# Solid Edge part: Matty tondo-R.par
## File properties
Title: Matty tondo/R
Author: DESYS
Template: Normal.par
Last saved by: i.fialdini
Revision: 7
Application: Solid Edge
Tipo di contenuto documento: 0
Precisione: 0,990
Document Number: 8055/R
Revision: 0
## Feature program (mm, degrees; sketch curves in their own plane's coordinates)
sketch for "unnamed RevolvedProtrusion 1" plane through (0, 0, 0) normal (0, -1, 0) x-axis (1, 0, 0)
  line (-103.4736, -287.9981) -> (-155.4991, -287.9981)
  arc centre (-155.4991, -282.9981) radius 5 from (-160, -285.1756) to (-155.4991, -287.9981) ccw
  arc centre (470.1318, 19.6751) radius 700 from (-229.7225, 5.3909) to (-160, -285.1756) ccw
  arc centre (-224.7235, 5.4929) radius 5 from (-223.4856, 10.3372) to (-229.7225, 5.3909) ccw
  line (-223.4856, 10.3372) -> (-198.051, 3.8378)
  arc centre (-199.2889, -1.0065) radius 5 from (-194.3913, 0.0001) to (-198.051, 3.8378) ccw
  arc centre (50.4896, 50.3322) radius 250 from (-194.3913, 0.0001) to (-25, -187.9981) ccw
  line (0, -187.9981) -> (-25, -187.9981)
  line (-30, -227.9981) -> (0, -227.9981)
  arc centre (-30, -222.9981) radius 5 from (-35, -222.9981) to (-30, -227.9981) ccw
  line (-35, -211.5908) -> (-35, -222.9981)
  arc centre (-40, -211.5908) radius 5 from (-35, -211.5908) to (-38.2474, -206.908) ccw
  arc centre (-20.7216, -160.0802) radius 50 from (-57.3248, -194.142) to (-38.2474, -206.908) ccw
  arc centre (-60.9851, -197.5482) radius 5 from (-57.3248, -194.142) to (-65.6708, -195.8034) ccw
  line (-98.7879, -284.7428) -> (-65.6708, -195.8034)
  arc centre (-103.4736, -282.9981) radius 5 from (-103.4736, -287.9981) to (-98.7879, -284.7428) ccw
revolve "unnamed RevolvedProtrusion 1" add full turn 360 deg about sketch line (0, -187.9981) -> (0, -227.9981)
sketch for "unnamed Protrusion 1" plane through (0, 0, 0) normal (0, 0, 1) x-axis (1, 0, 0)
  line (-160.4648, -109.7225) -> (160.4648, -109.7225)
extrude "unnamed Protrusion 1" add through along -normal
sketch for "unnamed RevolvedCutout 1" plane through (0, 0, 0) normal (1, 0, 0) x-axis (0, 1, 0)
  line (-227.1078, -42.4292) -> (-218.1082, -42.4292)
  arc centre (-218.1082, -32.4292) radius 10 from (-208.9001, -36.3292) to (-218.1082, -42.4292) cw
  line (-208.9001, -36.3292) -> (-202.1374, -20.3623)
  arc centre (-192.9293, -24.2623) radius 10 from (-202.1374, -20.3623) to (-192.9293, -14.2623) cw
  line (-192.9293, -14.2623) -> (-146.1087, -14.2623)
  arc centre (-146.1087, -24.2623) radius 10 from (-146.1087, -14.2623) to (-136.1087, -24.2623) cw
  line (-136.1087, -24.2623) -> (-136.1087, -135.0988)
  arc centre (-116.1087, -135.0988) radius 20 from (-136.1087, -135.0988) to (-130.3249, -149.1665) ccw
  line (-130.3249, -149.1665) -> (-70.73, -209.3904)
revolve "unnamed RevolvedCutout 1" cut finite
fillet "Rotondo_1" radius 5
fillet "Rotondo_2" radius 10
sketch for "Foro_1" plane through (0, 0, -187.9981) normal (0, 0, 1) x-axis (0, -1, 0)
  hole centre (0, 0) bore radius 25
hole "Foro_1" diameter 50 through
sketch for "Foro_2" plane through (0, -157.0547, 0) normal (0, 0, 1) x-axis (-1, 0, 0)
  hole centre (0, 12.6678) bore radius 17.5
hole "Foro_2" diameter 35 through
fillet "Rotondo_3" radius 3
fillet "Rotondo_4" radius 10
sketch for "Foro_3" plane through (0, 9.4953, -287.9981) normal (0, 0, -1) x-axis (0.461749, -0.887011, 0)
  hole centre (-49.0263, 114.7425) bore radius 7.5
hole "Foro_3" diameter 15 finite
sketch for "unnamed Hole 1" plane through (0, 9.4953, -287.9981) normal (0, 0, -1) x-axis (0.461749, -0.887011, 0)
  hole centre (66.141, -106.4919) bore radius 7.5
hole "unnamed Hole 1" finite
sketch for "unnamed Hole 2" plane through (0, 9.4953, -287.9981) normal (0, 0, -1) x-axis (0.461749, -0.887011, 0)
  hole centre (-102.4539, -53.3341) bore radius 7.5
hole "unnamed Hole 2" finite
pattern "unnamed Pattern 1" of "Foro_3", "unnamed Hole 1", "unnamed Hole 2"
sketch for "Foro_6" plane through (0, 0, 0) normal (0, -1, 0) x-axis (1, 0, 0)
  hole centre (0, -39.5071) bore radius 12.5
hole "Foro_6" diameter 25 to key point
fillet "Rotondo_6" radius 8
sketch for "ScavoEstrusione_2" plane through (0, 0, 0) normal (1, 0, 0) x-axis (0, 1, 0)
extrude "ScavoEstrusione_2" cut finite 133 symmetric
draft "Spoglia_1"  Angles1 = 6.8 deg
draft "Spoglia_2"  Angles1 = 6.8 deg
fillet "Rotondo_7" radius 5
sketch for "ExtrudedProtrusion_2" plane through (0, 0, 0) normal (1, 0, 0) x-axis (0, 1, 0)
  line (-148.2711, -139.7002) -> (-148.2711, -6.4859)
  line (-148.2711, -6.4859) -> (-126.4427, -6.4859)
  line (-126.4427, -6.4859) -> (-126.4427, -128.0458)
  line (-126.4427, -128.0458) -> (-88.0369, -175.6127)
  line (-88.0369, -175.6127) -> (-26.903, -195.8034)
  line (-26.903, -195.8034) -> (-26.903, -223.5492)
  line (-26.903, -223.5492) -> (-81.082, -219.8614)
  line (-81.082, -219.8614) -> (-148.2711, -139.7002)
extrude "ExtrudedProtrusion_2" add finite 30 symmetric
fillet "Rotondo_5" radius 5
fillet "Rotondo_8" radius 10
fillet "Rotondo_9" radius 5
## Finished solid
Body 1: solid body, 83 faces, 184 edges, 102 vertices.
  Faces by surface: cylinder 24, plane 22, torus 19, blend 12, sphere 4, cone 2
  Edges by curve: circle 76, intersection 49, line 49, ellipse 10
Bounding box of the edges (mm; curved faces can reach further): 459.445 x 459.445 x 298.335, from (-229.7225, -229.7225, -287.9981) to (229.7225, 229.7225, 10.3372).
Cylindrical faces by radius (mm): R5 x8, R7.5 x3, R10 x7, R12.5 x1, R17.5 x1, R20 x2, R25 x1, R35 x1
Conical faces (half-angle, radius in mm at the cone's reference point): 20.4231 deg R65.6708 x1, 75.6657 deg R223.4856 x1
Toroidal faces (ring radius, tube radius in mm): R-470.1318 r700 x1, R-50.4896 r250 x1, R5 r5 x4, R20.5 r3 x1, R20.7216 r50 x1, R30 r5 x1, R35 r10 x1, R40 r5 x1, R60.9851 r5 x1, R103.4736 r5 x1, R155.4991 r5 x1, R189.9144 r8 x2, R199.2889 r5 x1, R222.5183 r5 x1, R224.7235 r5 x1
Spherical faces by radius (mm): R5 x4
Planar faces by outward normal: +x 1, +y 2, +z 1, -x 1, -y 3, -z 7, oblique 7
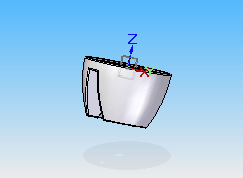
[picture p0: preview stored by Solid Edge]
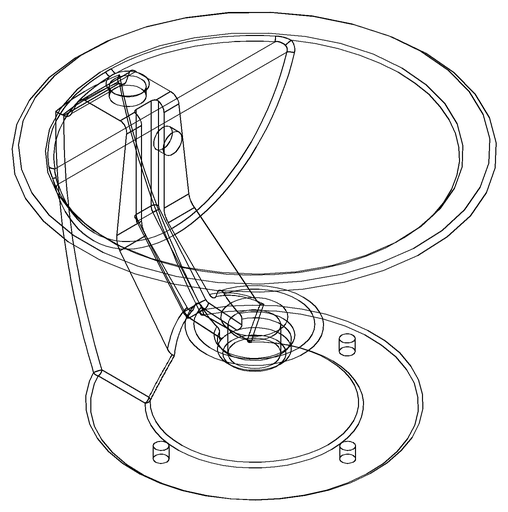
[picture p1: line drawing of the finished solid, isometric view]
